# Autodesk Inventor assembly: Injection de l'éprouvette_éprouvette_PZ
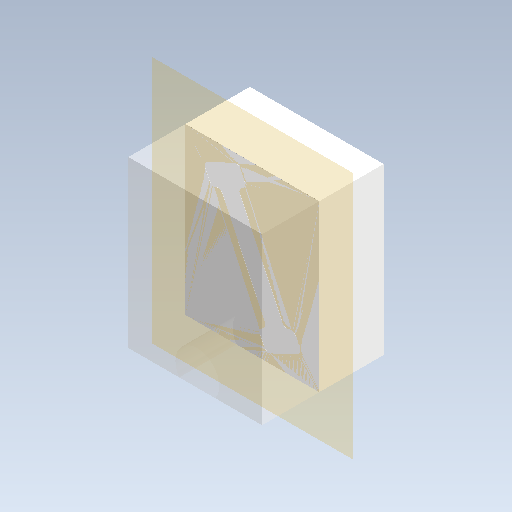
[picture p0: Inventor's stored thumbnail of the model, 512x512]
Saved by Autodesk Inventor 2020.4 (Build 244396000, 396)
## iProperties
Created: 2021-10
Part Number: Injection de l'éprouvette_éprouvette_PZ
Document SubType Name: Assembly
Designer: mel
Author: mel
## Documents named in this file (7)
- D:\travail\année 2020-2021\itec\prépa injection plastique eduscol\dossier de travail\Ensemble des pièces de l'activité\Conception de moule1\Injection de l'éprouvette_éprouvette_PZ.iam
- D:\travail\année 2020-2021\itec\prépa injection plastique eduscol\dossier de travail\Ensemble des pièces de l'activité\Conception de moule1\Injection de l'éprouvette_éprouvette_MP.ipt
- D:\travail\année 2020-2021\itec\prépa injection plastique eduscol\dossier de travail\Ensemble des pièces de l'activité\Conception de moule1\Injection de l'éprouvette_éprouvette_WP.ipt
- D:\travail\année 2020-2021\itec\prépa injection plastique eduscol\dossier de travail\Ensemble des pièces de l'activité\Conception de moule1\Injection de l'éprouvette_éprouvette_CR_Base.ipt
- D:\travail\année 2020-2021\itec\prépa injection plastique eduscol\dossier de travail\Ensemble des pièces de l'activité\Conception de moule1\Injection de l'éprouvette_éprouvette_CR_1.ipt
- D:\travail\année 2020-2021\itec\prépa injection plastique eduscol\dossier de travail\Ensemble des pièces de l'activité\Conception de moule1\Injection de l'éprouvette_éprouvette_CV_Base.ipt
- D:\travail\année 2020-2021\itec\prépa injection plastique eduscol\dossier de travail\Ensemble des pièces de l'activité\Conception de moule1\Injection de l'éprouvette_éprouvette_CV_1.ipt
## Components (6 placed, 6 different names)
1. Injection de l'éprouvette_éprouvette_MP:1 — Affleurement:1, Affleurement:2, Affleurement:3, Affleurement:4, Affleurement:5, Affleurement:6
2. Injection de l'éprouvette_éprouvette_WP:1 — Affleurement:4, Affleurement:5, Affleurement:6
3. Injection de l'éprouvette_éprouvette_CR_Base:1 — Affleurement:7, Affleurement:8, Affleurement:9, Affleurement:13, Affleurement:14, Affleurement:15
4. Injection de l'éprouvette_éprouvette_CR_1:1 — Affleurement:13, Affleurement:14, Affleurement:15
5. Injection de l'éprouvette_éprouvette_CV_Base:1 — Affleurement:10, Affleurement:11, Affleurement:12, Affleurement:16, Affleurement:17, Affleurement:18
6. Injection de l'éprouvette_éprouvette_CV_1:1 — Affleurement:16, Affleurement:17, Affleurement:18
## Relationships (18: Flush 18)
- Affleurement:1 [Flush]: Injection de l'éprouvette_éprouvette_MP:1
- Affleurement:2 [Flush]: Injection de l'éprouvette_éprouvette_MP:1
- Affleurement:3 [Flush]: Injection de l'éprouvette_éprouvette_MP:1
- Affleurement:4 [Flush]: Injection de l'éprouvette_éprouvette_MP:1 ↔ Injection de l'éprouvette_éprouvette_WP:1
- Affleurement:5 [Flush]: Injection de l'éprouvette_éprouvette_MP:1 ↔ Injection de l'éprouvette_éprouvette_WP:1
- Affleurement:6 [Flush]: Injection de l'éprouvette_éprouvette_MP:1 ↔ Injection de l'éprouvette_éprouvette_WP:1
- Affleurement:7 [Flush]: Injection de l'éprouvette_éprouvette_CR_Base:1
- Affleurement:8 [Flush]: Injection de l'éprouvette_éprouvette_CR_Base:1
- Affleurement:9 [Flush]: Injection de l'éprouvette_éprouvette_CR_Base:1
- Affleurement:10 [Flush]: Injection de l'éprouvette_éprouvette_CV_Base:1
- Affleurement:11 [Flush]: Injection de l'éprouvette_éprouvette_CV_Base:1
- Affleurement:12 [Flush]: Injection de l'éprouvette_éprouvette_CV_Base:1
- Affleurement:13 [Flush]: Injection de l'éprouvette_éprouvette_CR_Base:1 ↔ Injection de l'éprouvette_éprouvette_CR_1:1
- Affleurement:14 [Flush]: Injection de l'éprouvette_éprouvette_CR_Base:1 ↔ Injection de l'éprouvette_éprouvette_CR_1:1
- Affleurement:15 [Flush]: Injection de l'éprouvette_éprouvette_CR_Base:1 ↔ Injection de l'éprouvette_éprouvette_CR_1:1
- Affleurement:16 [Flush]: Injection de l'éprouvette_éprouvette_CV_Base:1 ↔ Injection de l'éprouvette_éprouvette_CV_1:1
- Affleurement:17 [Flush]: Injection de l'éprouvette_éprouvette_CV_Base:1 ↔ Injection de l'éprouvette_éprouvette_CV_1:1
- Affleurement:18 [Flush]: Injection de l'éprouvette_éprouvette_CV_Base:1 ↔ Injection de l'éprouvette_éprouvette_CV_1:1
